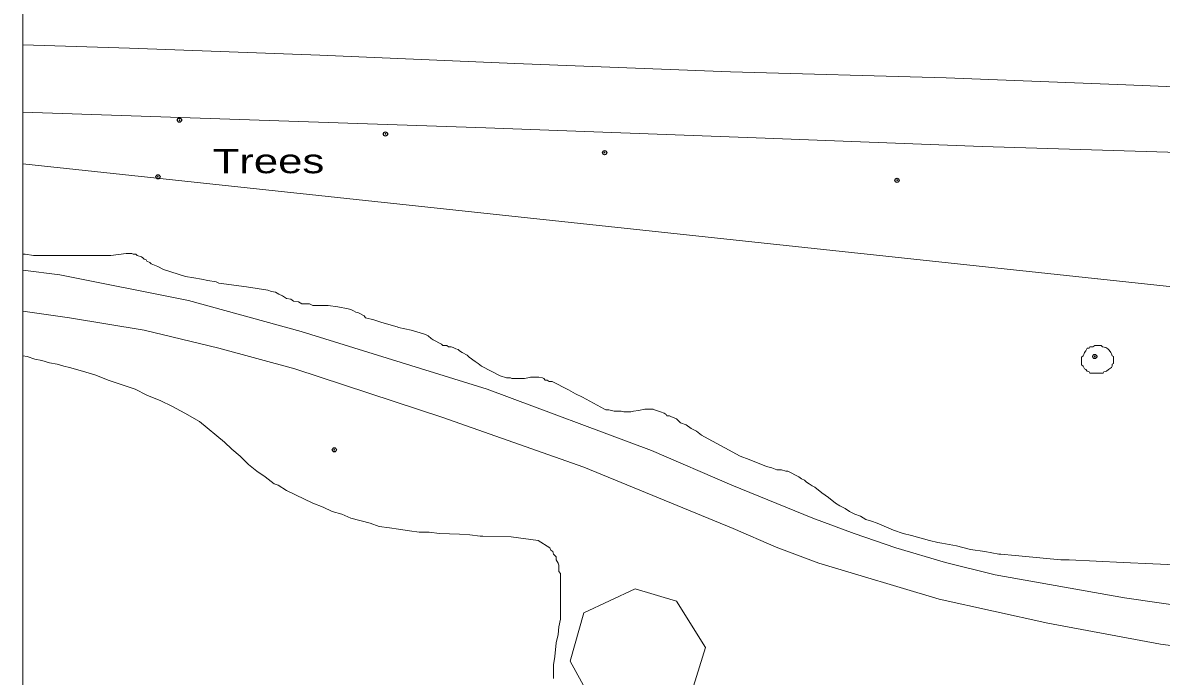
# Model space of a CAD drawing. Extents: x 528790 to 529292, y 179350 to 179856.
# Drawn here: x 528790.2 to 528872.6, y 179733.5 to 179780.7 of the extents above; entities that cross this region are included whole.
import ezdxf

# ---------------------------------------------------------------- set-up
doc = ezdxf.new("R2010")
doc.units = 0
doc.header["$LTSCALE"] = 0.6
doc.header["$PDMODE"] = 32
doc.header["$PDSIZE"] = 0.3
for name, color, linetype, lineweight in [('1', 7, 'Continuous', 13), ('2', 7, 'Continuous', 13), ('7', 7, 'Continuous', 13)]:
    doc.layers.add(name, color=color, linetype=linetype, lineweight=lineweight)
for name, color, linetype in [('3', 7, 'Continuous'), ('4', 7, 'Continuous'), ('5', 7, 'Continuous')]:
    doc.layers.add(name, color=color, linetype=linetype)

msp = doc.modelspace()

# ---------------------------------------------------------------- linework, layer by layer
at = {"layer": '1'}
for points in [[(528995.96, 179785.29), (528808.03, 179792.34), (528790.22, 179792.969), (528790.22, 179779.158), (528797.95, 179778.9), (528811.7, 179778.4), (528825.8, 179777.8), (528841.4, 179777.2), (528857, 179776.75), (528870, 179776.25), (528881.15, 179775.8), (528894.6, 179775.5), (528906.6, 179775.1), (528919, 179774.6), (528934.8, 179774), (528959.55, 179773)], [(528959.55, 179773), (528934.8, 179774), (528919, 179774.6), (528906.6, 179775.1), (528894.6, 179775.5), (528881.15, 179775.8), (528870, 179776.25), (528857, 179776.75), (528841.4, 179777.2), (528825.8, 179777.8), (528811.7, 179778.4), (528797.95, 179778.9), (528790.22, 179779.158), (528790.22, 179774.277), (528823.7, 179773.15), (528843.9, 179772.4), (528859.6, 179771.8), (528880.95, 179771.15), (528896.6, 179770.5), (528913.4, 179770), (528929.35, 179769.4), (528948.5, 179768.8), (528965.3, 179768.3)], [(528965.3, 179768.3), (528948.5, 179768.8), (528929.35, 179769.4), (528913.4, 179770), (528896.6, 179770.5), (528880.95, 179771.15), (528859.6, 179771.8), (528843.9, 179772.4), (528823.7, 179773.15), (528790.22, 179774.277), (528790.22, 179770.55), (528945.7, 179753.9), (528948.6, 179753.65), (528951.55, 179753.55), (528957.8, 179753.8)], [(528790.22, 179770.55), (528790.22, 179764), (528790.4, 179764), (528791, 179763.9), (528796.6, 179763.9), (528797.7, 179764.05), (528798.1, 179764.05), (528798.2, 179764), (528798.4, 179764), (528798.5, 179763.9), (528798.8, 179763.8), (528798.9, 179763.75), (528799, 179763.65), (528799.15, 179763.6), (528799.2, 179763.5), (528799.4, 179763.4), (528799.5, 179763.3), (528800, 179763.1), (528800.4, 179762.9), (528802, 179762.4), (528802.6, 179762.3), (528803.15, 179762.2), (528803.6, 179762.1), (528804.2, 179762), (528804.4, 179761.9), (528806.4, 179761.65), (528807.95, 179761.4), (528808.2, 179761.3), (528808.5, 179761.25), (528808.75, 179761.1), (528809, 179761), (528809.3, 179760.8), (528809.6, 179760.75), (528809.8, 179760.6), (528810.15, 179760.55), (528810.4, 179760.4), (528810.95, 179760.4), (528811.2, 179760.3), (528812.3, 179760.3), (528813, 179760.2), (528813.75, 179760.05), (528813.95, 179760), (528814.15, 179759.9), (528814.3, 179759.8), (528814.5, 179759.75), (528814.9, 179759.55), (528815, 179759.4), (528815.6, 179759.25), (528816.2, 179759.05), (528817.3, 179758.75), (528817.4, 179758.7), (528818.3, 179758.5), (528819.2, 179758.25), (528819.35, 179758.2), (528819.55, 179758.1), (528819.75, 179757.9), (528819.9, 179757.8), (528820.5, 179757.5), (528820.6, 179757.4), (528820.9, 179757.4), (528821, 179757.3), (528821.2, 179757.3), (528821.35, 179757.25), (528821.55, 179757.15), (528821.7, 179757.1), (528821.8, 179757), (528822, 179756.9), (528822.35, 179756.7), (528822.5, 179756.55), (528822.95, 179756.25), (528823.15, 179756.1), (528823.4, 179755.9), (528824.75, 179755.2), (528825.2, 179755.05), (528825.5, 179755.05), (528825.6, 179755), (528826.5, 179755), (528826.75, 179755.05), (528826.95, 179755.1), (528827.55, 179755.1), (528827.8, 179755.05), (528827.9, 179755), (528828, 179754.9), (528828.15, 179754.9), (528828.3, 179754.8), (528828.5, 179754.8), (528829.7, 179754.2), (528830.2, 179753.9), (528830.7, 179753.65), (528832.3, 179752.8), (528832.4, 179752.75), (528832.6, 179752.75), (528833, 179752.65), (528833.5, 179752.65), (528833.7, 179752.6), (528834.2, 179752.6), (528834.4, 179752.65), (528834.75, 179752.7), (528835.2, 179752.8), (528835.8, 179752.8), (528835.9, 179752.75)], [(528957.8, 179753.8), (528951.55, 179753.55), (528948.6, 179753.65), (528945.7, 179753.9), (528790.22, 179770.55)], [(528809.3, 179760.8), (528809, 179761), (528808.75, 179761.1), (528808.5, 179761.25), (528808.2, 179761.3), (528807.95, 179761.4), (528806.4, 179761.65), (528804.4, 179761.9), (528804.2, 179762), (528803.6, 179762.1), (528803.15, 179762.2), (528802.6, 179762.3), (528802, 179762.4), (528800.4, 179762.9), (528800, 179763.1), (528799.5, 179763.3), (528799.4, 179763.4), (528799.2, 179763.5), (528799.15, 179763.6), (528799, 179763.65), (528798.9, 179763.75), (528798.8, 179763.8), (528798.5, 179763.9), (528798.4, 179764), (528798.2, 179764), (528798.1, 179764.05), (528797.7, 179764.05), (528796.6, 179763.9), (528791, 179763.9), (528790.4, 179764), (528790.22, 179764)], [(528790.22, 179764), (528790.22, 179762.852), (528792.9, 179762.5), (528802.2, 179760.65), (528810.35, 179758.4), (528823.8, 179754.25), (528835.7, 179749.8), (528841.5, 179747.3), (528847.35, 179744.9), (528850.35, 179743.8), (528853.35, 179742.75), (528856.95, 179741.7), (528860.55, 179740.8), (528869.9, 179739.15), (528879.6, 179737.75)], [(528879.6, 179737.75), (528869.9, 179739.15), (528860.55, 179740.8), (528856.95, 179741.7), (528853.35, 179742.75), (528850.35, 179743.8), (528847.35, 179744.9), (528841.5, 179747.3), (528835.7, 179749.8), (528823.8, 179754.25), (528810.35, 179758.4), (528802.2, 179760.65), (528792.9, 179762.5), (528790.22, 179762.852), (528790.22, 179759.878), (528793.6, 179759.4), (528799, 179758.5), (528804.4, 179757.2), (528809.9, 179755.7), (528820.6, 179752.2), (528830.8, 179748.6), (528841.6, 179744.15), (528844.7, 179742.8), (528847.8, 179741.65), (528856.5, 179739.05), (528864.35, 179737.3), (528872.5, 179735.8), (528883.75, 179734.3)], [(528848.5, 179746.4), (528848, 179746.75), (528847.5, 179747.15), (528847.3, 179747.25), (528847.1, 179747.4), (528846.9, 179747.5), (528846.75, 179747.65), (528846.55, 179747.75), (528846.35, 179747.9), (528845.55, 179748.3), (528845.4, 179748.3), (528845.1, 179748.4), (528844.75, 179748.4), (528844.4, 179748.55), (528844, 179748.65), (528842.75, 179749.15), (528842.1, 179749.4), (528841, 179750), (528839.8, 179750.65), (528839.3, 179750.9), (528838.95, 179751.2), (528838.55, 179751.4), (528838.2, 179751.65), (528837.8, 179751.8), (528837.5, 179752.1), (528837.1, 179752.25), (528837, 179752.3), (528836.8, 179752.3), (528836.75, 179752.4), (528836.6, 179752.5), (528836.35, 179752.6), (528835.9, 179752.75), (528835.8, 179752.8), (528835.2, 179752.8), (528834.75, 179752.7), (528834.4, 179752.65), (528834.2, 179752.6), (528833.7, 179752.6), (528833.5, 179752.65), (528833, 179752.65), (528832.6, 179752.75), (528832.4, 179752.75), (528832.3, 179752.8), (528830.7, 179753.65), (528830.2, 179753.9), (528829.7, 179754.2), (528828.5, 179754.8), (528828.3, 179754.8), (528828.15, 179754.9), (528828, 179754.9), (528827.9, 179755), (528827.8, 179755.05), (528827.55, 179755.1), (528826.95, 179755.1), (528826.75, 179755.05), (528826.5, 179755), (528825.6, 179755), (528825.5, 179755.05), (528825.2, 179755.05), (528824.75, 179755.2), (528823.4, 179755.9), (528823.15, 179756.1), (528822.95, 179756.25), (528822.5, 179756.55), (528822.35, 179756.7), (528822, 179756.9), (528821.8, 179757), (528821.7, 179757.1), (528821.55, 179757.15), (528821.35, 179757.25), (528821.2, 179757.3), (528821, 179757.3), (528820.9, 179757.4), (528820.6, 179757.4), (528820.5, 179757.5), (528819.9, 179757.8), (528819.75, 179757.9), (528819.55, 179758.1), (528819.35, 179758.2), (528819.2, 179758.25), (528818.3, 179758.5), (528817.4, 179758.7), (528817.3, 179758.75), (528816.2, 179759.05), (528815.6, 179759.25), (528815, 179759.4), (528814.9, 179759.55), (528814.5, 179759.75), (528814.3, 179759.8), (528814.15, 179759.9), (528813.95, 179760), (528813.75, 179760.05), (528813, 179760.2), (528812.3, 179760.3), (528811.2, 179760.3), (528810.95, 179760.4), (528810.4, 179760.4), (528810.15, 179760.55), (528809.8, 179760.6), (528809.6, 179760.75), (528809.3, 179760.8)], [(528883.75, 179734.3), (528872.5, 179735.8), (528864.35, 179737.3), (528856.5, 179739.05), (528847.8, 179741.65), (528844.7, 179742.8), (528841.6, 179744.15), (528830.8, 179748.6), (528820.6, 179752.2), (528809.9, 179755.7), (528804.4, 179757.2), (528799, 179758.5), (528793.6, 179759.4), (528790.22, 179759.878), (528790.22, 179756.66)], [(528828.6, 179733.3), (528828.6, 179734.3), (528828.7, 179734.9), (528828.8, 179735.9), (528828.95, 179736.5), (528829, 179737.05), (528829.1, 179737.6), (528829.1, 179740.9), (528829, 179741.05), (528829, 179741.5), (528828.95, 179741.65), (528828.8, 179741.9), (528828.8, 179742.1), (528828.6, 179742.3), (528828.55, 179742.5), (528828.4, 179742.6), (528828.35, 179742.75), (528827.5, 179743.3), (528825.55, 179743.55), (528823.5, 179743.6), (528823.3, 179743.6), (528822.55, 179743.7), (528821.8, 179743.75), (528820.35, 179743.8), (528819.6, 179743.9), (528818.9, 179743.9), (528818.2, 179744), (528817.4, 179744.1), (528816.75, 179744.2), (528816, 179744.3), (528815.35, 179744.55), (528813.95, 179744.9), (528813.3, 179745.2), (528812.6, 179745.4), (528811.95, 179745.7), (528811.2, 179746), (528809.95, 179746.6), (528809.3, 179746.9), (528808.7, 179747.3), (528808.4, 179747.4), (528807.75, 179747.9), (528807.15, 179748.3), (528806.55, 179748.8), (528805.95, 179749.4), (528805.35, 179749.9), (528804.8, 179750.4), (528803, 179751.9), (528801.95, 179752.5), (528801, 179753), (528800.2, 179753.4), (528799.2, 179753.8), (528798.35, 179754.25), (528796.4, 179754.9), (528795.5, 179755.25), (528794.55, 179755.55), (528793.6, 179755.8), (528793.2, 179755.9), (528792.7, 179756.05), (528792.15, 179756.15), (528791.6, 179756.3), (528791.1, 179756.4), (528790.55, 179756.6), (528790.22, 179756.66), (528790.22, 179732.644)], [(528790.22, 179756.66), (528790.55, 179756.6), (528791.1, 179756.4), (528791.6, 179756.3), (528792.15, 179756.15), (528792.7, 179756.05), (528793.2, 179755.9), (528793.6, 179755.8), (528794.55, 179755.55), (528795.5, 179755.25), (528796.4, 179754.9), (528798.35, 179754.25), (528799.2, 179753.8), (528800.2, 179753.4), (528801, 179753), (528801.95, 179752.5), (528803, 179751.9), (528804.8, 179750.4), (528805.35, 179749.9), (528805.95, 179749.4), (528806.55, 179748.8), (528807.15, 179748.3), (528807.75, 179747.9), (528808.4, 179747.4), (528808.7, 179747.3), (528809.3, 179746.9), (528809.95, 179746.6), (528811.2, 179746), (528811.95, 179745.7), (528812.6, 179745.4), (528813.3, 179745.2), (528813.95, 179744.9), (528815.35, 179744.55), (528816, 179744.3), (528816.75, 179744.2), (528817.4, 179744.1), (528818.2, 179744), (528818.9, 179743.9), (528819.6, 179743.9), (528820.35, 179743.8), (528821.8, 179743.75), (528822.55, 179743.7), (528823.3, 179743.6), (528823.5, 179743.6), (528825.55, 179743.55), (528827.5, 179743.3), (528828.35, 179742.75), (528828.4, 179742.6), (528828.55, 179742.5), (528828.6, 179742.3), (528828.8, 179742.1), (528828.8, 179741.9), (528828.95, 179741.65), (528829, 179741.5), (528829, 179741.05), (528829.1, 179740.9), (528829.1, 179737.6), (528829, 179737.05), (528828.95, 179736.5), (528828.8, 179735.9), (528828.7, 179734.9), (528828.6, 179734.3), (528828.6, 179733.3)], [(528835.9, 179752.75), (528836.35, 179752.6), (528836.6, 179752.5), (528836.75, 179752.4), (528836.8, 179752.3), (528837, 179752.3), (528837.1, 179752.25), (528837.5, 179752.1), (528837.8, 179751.8), (528838.2, 179751.65), (528838.55, 179751.4), (528838.95, 179751.2), (528839.3, 179750.9), (528839.8, 179750.65), (528841, 179750), (528842.1, 179749.4), (528842.75, 179749.15), (528844, 179748.65), (528844.4, 179748.55), (528844.75, 179748.4), (528845.1, 179748.4), (528845.4, 179748.3), (528845.55, 179748.3), (528846.35, 179747.9), (528846.55, 179747.75), (528846.75, 179747.65), (528846.9, 179747.5), (528847.1, 179747.4), (528847.3, 179747.25), (528847.5, 179747.15), (528848, 179746.75), (528848.5, 179746.4), (528849, 179746), (528849.3, 179745.8), (528849.7, 179745.6), (528850, 179745.4), (528850.4, 179745.2), (528850.8, 179745.05), (528851.2, 179744.8), (528851.6, 179744.7), (528852, 179744.55), (528853.2, 179744.05), (528853.9, 179743.8), (528854.5, 179743.65), (528855.8, 179743.3), (528856.4, 179743.15), (528856.7, 179743.1), (528857.75, 179742.9), (528858.75, 179742.65), (528859.8, 179742.5), (528860.8, 179742.3), (528860.95, 179742.3), (528862, 179742.2), (528865.3, 179741.9), (528865.9, 179741.9), (528869.8, 179741.7), (528871.95, 179741.6), (528879, 179741.3)], [(528879, 179741.3), (528871.95, 179741.6), (528869.8, 179741.7), (528865.9, 179741.9), (528865.3, 179741.9), (528862, 179742.2), (528860.95, 179742.3), (528860.8, 179742.3), (528859.8, 179742.5), (528858.75, 179742.65), (528857.75, 179742.9), (528856.7, 179743.1), (528856.4, 179743.15), (528855.8, 179743.3), (528854.5, 179743.65), (528853.9, 179743.8), (528853.2, 179744.05), (528852, 179744.55), (528851.6, 179744.7), (528851.2, 179744.8), (528850.8, 179745.05), (528850.4, 179745.2), (528850, 179745.4), (528849.7, 179745.6), (528849.3, 179745.8), (528849, 179746), (528848.5, 179746.4)]]:
    msp.add_lwpolyline(points, dxfattribs=at)
for points in [[(528868.35, 179755.4), (528868.4, 179755.5), (528868.6, 179755.55), (528868.75, 179755.65), (528868.95, 179755.8), (528869, 179755.9), (528869, 179756.05), (528869.1, 179756.1), (528869.1, 179756.6), (528869, 179756.65), (528868.95, 179756.8), (528868.9, 179756.9), (528868.8, 179757.05), (528868.7, 179757.15), (528868.55, 179757.25), (528868.3, 179757.3), (528868.2, 179757.4), (528867.75, 179757.4), (528867.6, 179757.3), (528867.4, 179757.3), (528867.35, 179757.2), (528867.2, 179757.2), (528867.1, 179757), (528867, 179756.9), (528866.95, 179756.75), (528866.9, 179756.65), (528866.8, 179756.55), (528866.8, 179756), (528866.9, 179755.9), (528867, 179755.7), (528867.1, 179755.65), (528867.2, 179755.55), (528867.35, 179755.5), (528867.4, 179755.4)], [(528867.75, 179757.4), (528868.2, 179757.4), (528868.3, 179757.3), (528868.55, 179757.25), (528868.7, 179757.15), (528868.8, 179757.05), (528868.9, 179756.9), (528868.95, 179756.8), (528869, 179756.65), (528869.1, 179756.6), (528869.1, 179756.1), (528869, 179756.05), (528869, 179755.9), (528868.95, 179755.8), (528868.75, 179755.65), (528868.6, 179755.55), (528868.4, 179755.5), (528868.35, 179755.4), (528867.4, 179755.4), (528867.35, 179755.5), (528867.2, 179755.55), (528867.1, 179755.65), (528867, 179755.7), (528866.9, 179755.9), (528866.8, 179756), (528866.8, 179756.55), (528866.9, 179756.65), (528866.95, 179756.75), (528867, 179756.9), (528867.1, 179757), (528867.2, 179757.2), (528867.35, 179757.2), (528867.4, 179757.3), (528867.6, 179757.3)], [(528835.15, 179730.3), (528838.5, 179732.05), (528839.6, 179735.55), (528837.5, 179738.9), (528834.5, 179739.8), (528830.8, 179738.05), (528829.8, 179734.55), (528831.6, 179731.3)], [(528835.15, 179730.3), (528831.6, 179731.3), (528829.8, 179734.55), (528830.8, 179738.05), (528834.5, 179739.8), (528837.5, 179738.9), (528839.6, 179735.55), (528838.5, 179732.05)]]:
    msp.add_lwpolyline(points, close=True, dxfattribs=at)
at = {"layer": '2'}
for points in [[(528790.22, 179779.158), (528797.95, 179778.9), (528811.7, 179778.4), (528825.8, 179777.8), (528841.4, 179777.2), (528857, 179776.75), (528870, 179776.25), (528881.15, 179775.8), (528894.6, 179775.5), (528906.6, 179775.1), (528919, 179774.6), (528934.8, 179774), (528959.55, 179773)], [(528790.22, 179774.277), (528823.7, 179773.15), (528843.9, 179772.4), (528859.6, 179771.8), (528880.95, 179771.15), (528896.6, 179770.5), (528913.4, 179770), (528929.35, 179769.4), (528948.5, 179768.8), (528965.3, 179768.3), (528977.883, 179767.816), (528980.9, 179767.7), (528988.1, 179767.35), (529000, 179767.03), (529025.95, 179766.25), (529028.05, 179766.15), (529028.95, 179766.05), (529029.6, 179766.05), (529029.75, 179766), (529029.8, 179765.9), (529030.2, 179765.6)], [(528790.22, 179770.55), (528945.7, 179753.9), (528948.6, 179753.65), (528951.55, 179753.55), (528957.8, 179753.8), (528964.2, 179754.4), (528972.37, 179756.13)], [(528790.22, 179764), (528790.4, 179764), (528791, 179763.9), (528796.6, 179763.9), (528797.7, 179764.05), (528798.1, 179764.05), (528798.2, 179764), (528798.4, 179764), (528798.5, 179763.9), (528798.8, 179763.8), (528798.9, 179763.75), (528799, 179763.65), (528799.15, 179763.6), (528799.2, 179763.5), (528799.4, 179763.4), (528799.5, 179763.3), (528800, 179763.1), (528800.4, 179762.9), (528802, 179762.4), (528802.6, 179762.3), (528803.15, 179762.2), (528803.6, 179762.1), (528804.2, 179762), (528804.4, 179761.9), (528806.4, 179761.65), (528807.95, 179761.4), (528808.2, 179761.3), (528808.5, 179761.25), (528808.75, 179761.1), (528809, 179761), (528809.3, 179760.8), (528809.6, 179760.75), (528809.8, 179760.6), (528810.15, 179760.55), (528810.4, 179760.4), (528810.95, 179760.4), (528811.2, 179760.3), (528812.3, 179760.3), (528813, 179760.2), (528813.75, 179760.05), (528813.95, 179760), (528814.15, 179759.9), (528814.3, 179759.8), (528814.5, 179759.75), (528814.9, 179759.55), (528815, 179759.4), (528815.6, 179759.25), (528816.2, 179759.05), (528817.3, 179758.75), (528817.4, 179758.7), (528818.3, 179758.5), (528819.2, 179758.25), (528819.35, 179758.2), (528819.55, 179758.1), (528819.75, 179757.9), (528819.9, 179757.8), (528820.5, 179757.5), (528820.6, 179757.4), (528820.9, 179757.4), (528821, 179757.3), (528821.2, 179757.3), (528821.35, 179757.25), (528821.55, 179757.15), (528821.7, 179757.1), (528821.8, 179757), (528822, 179756.9), (528822.35, 179756.7), (528822.5, 179756.55), (528822.95, 179756.25), (528823.15, 179756.1), (528823.4, 179755.9), (528824.75, 179755.2), (528825.2, 179755.05), (528825.5, 179755.05), (528825.6, 179755), (528826.5, 179755), (528826.75, 179755.05), (528826.95, 179755.1), (528827.55, 179755.1), (528827.8, 179755.05), (528827.9, 179755), (528828, 179754.9), (528828.15, 179754.9), (528828.3, 179754.8), (528828.5, 179754.8), (528829.7, 179754.2), (528830.2, 179753.9), (528830.7, 179753.65), (528832.3, 179752.8), (528832.4, 179752.75), (528832.6, 179752.75), (528833, 179752.65), (528833.5, 179752.65), (528833.7, 179752.6), (528834.2, 179752.6), (528834.4, 179752.65), (528834.75, 179752.7), (528835.2, 179752.8), (528835.8, 179752.8), (528835.9, 179752.75), (528836.35, 179752.6)], [(528790.22, 179762.852), (528792.9, 179762.5), (528802.2, 179760.65), (528810.35, 179758.4), (528823.8, 179754.25), (528835.7, 179749.8), (528841.5, 179747.3), (528847.35, 179744.9), (528850.35, 179743.8), (528853.35, 179742.75), (528856.95, 179741.7), (528860.55, 179740.8), (528869.9, 179739.15), (528879.6, 179737.75)], [(528790.22, 179759.878), (528793.6, 179759.4), (528799, 179758.5), (528804.4, 179757.2), (528809.9, 179755.7), (528820.6, 179752.2), (528830.8, 179748.6), (528841.6, 179744.15), (528844.7, 179742.8), (528847.8, 179741.65), (528856.5, 179739.05), (528864.35, 179737.3), (528872.5, 179735.8), (528883.75, 179734.3)], [(528790.22, 179756.66), (528790.55, 179756.6), (528791.1, 179756.4), (528791.6, 179756.3), (528792.15, 179756.15), (528792.7, 179756.05), (528793.2, 179755.9), (528793.6, 179755.8), (528794.55, 179755.55), (528795.5, 179755.25), (528796.4, 179754.9), (528798.35, 179754.25), (528799.2, 179753.8), (528800.2, 179753.4), (528801, 179753), (528801.95, 179752.5), (528803, 179751.9), (528804.8, 179750.4), (528805.35, 179749.9), (528805.95, 179749.4), (528806.55, 179748.8), (528807.15, 179748.3), (528807.75, 179747.9), (528808.4, 179747.4), (528808.7, 179747.3), (528809.3, 179746.9), (528809.95, 179746.6), (528811.2, 179746), (528811.95, 179745.7), (528812.6, 179745.4), (528813.3, 179745.2), (528813.95, 179744.9), (528815.35, 179744.55), (528816, 179744.3), (528816.75, 179744.2), (528817.4, 179744.1), (528818.2, 179744), (528818.9, 179743.9), (528819.6, 179743.9), (528820.35, 179743.8), (528821.8, 179743.75), (528822.55, 179743.7), (528823.3, 179743.6), (528823.5, 179743.6), (528825.55, 179743.55), (528827.5, 179743.3), (528828.35, 179742.75), (528828.4, 179742.6), (528828.55, 179742.5), (528828.6, 179742.3), (528828.8, 179742.1), (528828.8, 179741.9), (528828.95, 179741.65), (528829, 179741.5), (528829, 179741.05), (528829.1, 179740.9), (528829.1, 179737.6), (528829, 179737.05), (528828.95, 179736.5), (528828.8, 179735.9), (528828.7, 179734.9), (528828.6, 179734.3), (528828.6, 179733.3)], [(528836.35, 179752.6), (528836.6, 179752.5), (528836.75, 179752.4), (528836.8, 179752.3), (528837, 179752.3), (528837.1, 179752.25), (528837.5, 179752.1), (528837.8, 179751.8), (528838.2, 179751.65), (528838.55, 179751.4), (528838.95, 179751.2), (528839.3, 179750.9), (528839.8, 179750.65), (528841, 179750), (528842.1, 179749.4), (528842.75, 179749.15), (528844, 179748.65), (528844.4, 179748.55), (528844.75, 179748.4), (528845.1, 179748.4), (528845.4, 179748.3), (528845.55, 179748.3), (528846.35, 179747.9), (528846.55, 179747.75), (528846.75, 179747.65), (528846.9, 179747.5), (528847.1, 179747.4), (528847.3, 179747.25), (528847.5, 179747.15), (528848, 179746.75), (528848.5, 179746.4), (528849, 179746), (528849.3, 179745.8), (528849.7, 179745.6), (528850, 179745.4), (528850.4, 179745.2), (528850.8, 179745.05), (528851.2, 179744.8), (528851.6, 179744.7), (528852, 179744.55), (528853.2, 179744.05), (528853.9, 179743.8), (528854.5, 179743.65), (528855.8, 179743.3), (528856.4, 179743.15), (528856.7, 179743.1), (528857.75, 179742.9), (528858.75, 179742.65), (528859.8, 179742.5), (528860.8, 179742.3), (528860.95, 179742.3), (528862, 179742.2), (528865.3, 179741.9), (528865.9, 179741.9), (528869.8, 179741.7), (528871.95, 179741.6), (528879, 179741.3)]]:
    msp.add_lwpolyline(points, dxfattribs=at)
for points in [[(528868.35, 179755.4), (528867.4, 179755.4), (528867.35, 179755.5), (528867.2, 179755.55), (528867.1, 179755.65), (528867, 179755.7), (528866.9, 179755.9), (528866.8, 179756), (528866.8, 179756.55), (528866.9, 179756.65), (528866.95, 179756.75), (528867, 179756.9), (528867.1, 179757), (528867.2, 179757.2), (528867.35, 179757.2), (528867.4, 179757.3), (528867.6, 179757.3), (528867.75, 179757.4), (528868.2, 179757.4), (528868.3, 179757.3), (528868.55, 179757.25), (528868.7, 179757.15), (528868.8, 179757.05), (528868.9, 179756.9), (528868.95, 179756.8), (528869, 179756.65), (528869.1, 179756.6), (528869.1, 179756.1), (528869, 179756.05), (528869, 179755.9), (528868.95, 179755.8), (528868.75, 179755.65), (528868.6, 179755.55), (528868.4, 179755.5)], [(528835.15, 179730.3), (528831.6, 179731.3), (528829.8, 179734.55), (528830.8, 179738.05), (528834.5, 179739.8), (528837.5, 179738.9), (528839.6, 179735.55), (528838.5, 179732.05)]]:
    msp.add_lwpolyline(points, close=True, dxfattribs=at)
at = {"layer": '3'}
for p in [(528801.55, 179773.7), (528816.45, 179772.7), (528832.3, 179771.35), (528853.45, 179769.35), (528867.75, 179756.6), (528812.75, 179749.85)]:
    msp.add_point(p, dxfattribs=at)
at = {"layer": '4'}
msp.add_point((528800, 179769.6), dxfattribs=at)
at = {"layer": '7'}
msp.add_lwpolyline([(528790.22, 179356.024), (529290.22, 179356.024), (529290.22, 179856.024), (528790.22, 179856.024)], close=True, dxfattribs=at)

# ---------------------------------------------------------------- texts
at = {"layer": '5', "width": 1.35}
msp.add_text('Trees', height=1.75, dxfattribs=at).set_placement((528803.95, 179769.86))

doc.saveas('drawing.dxf')
